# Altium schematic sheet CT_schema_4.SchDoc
size 334 x 183 mm
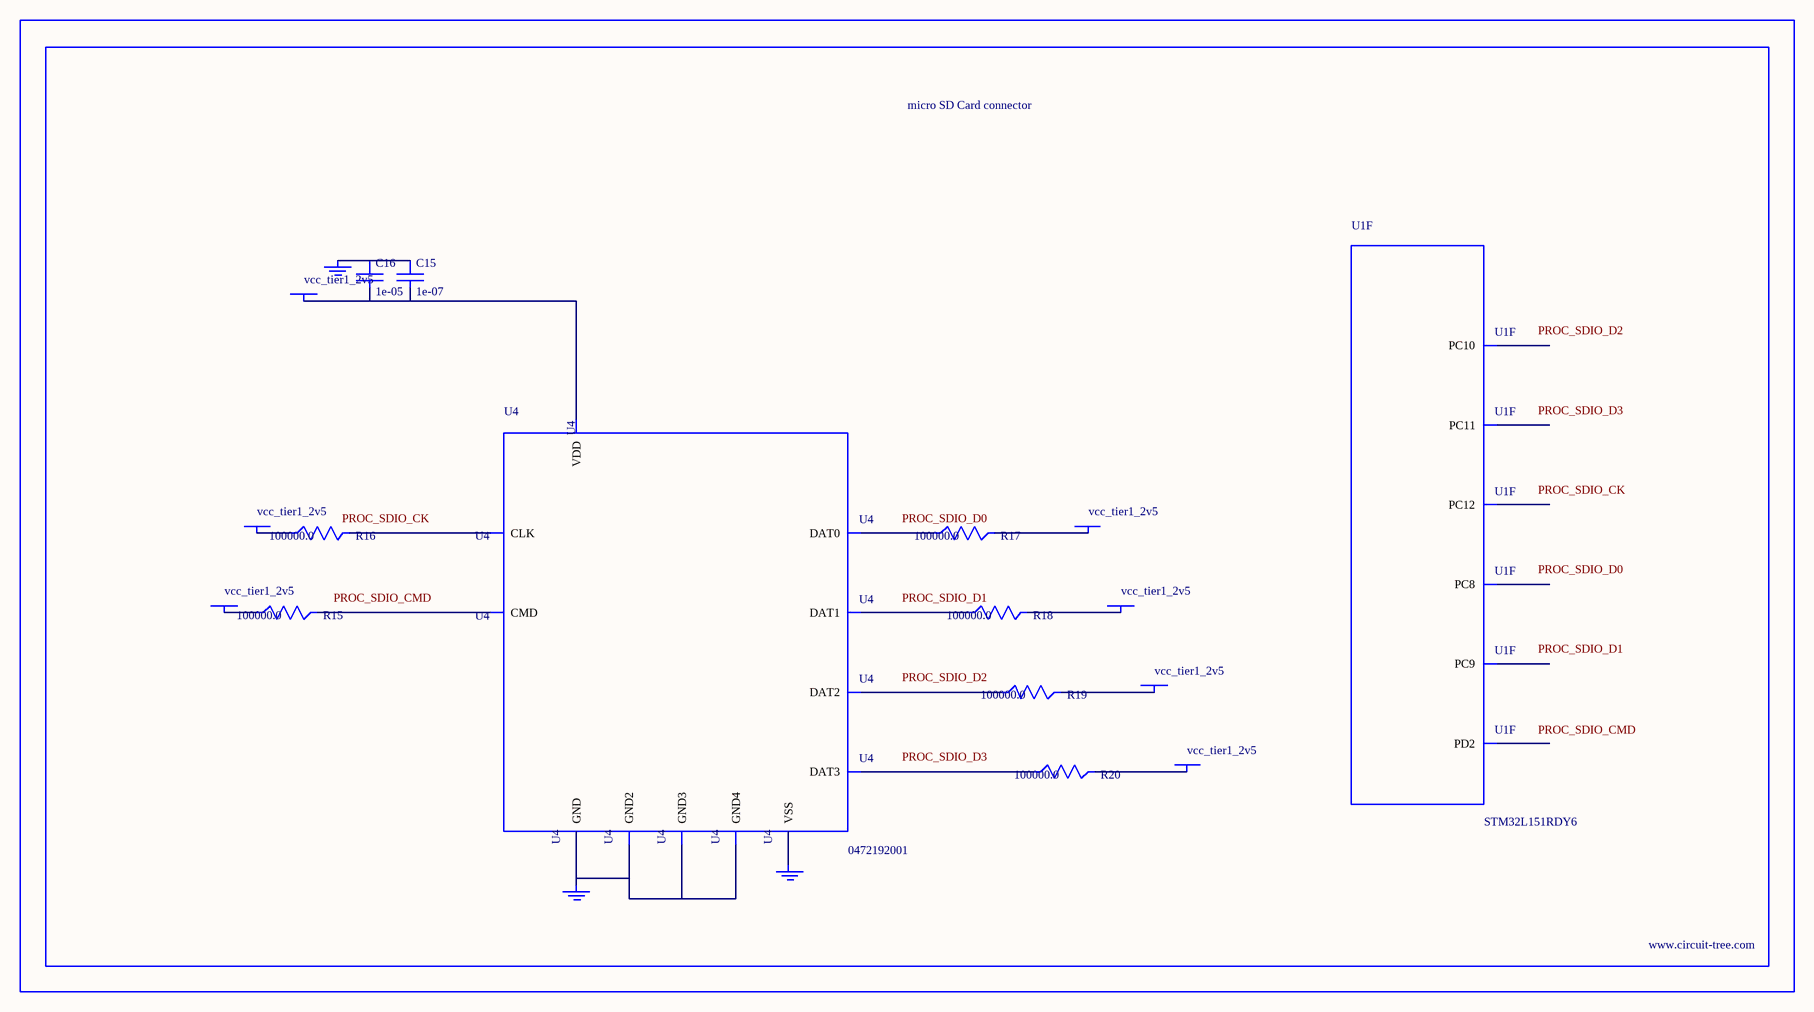
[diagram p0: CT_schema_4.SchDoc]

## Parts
BORDER3  (no value)
C15  1e-07  [C0402]
C16  1e-05  [C0805]
GND_INSTANCE_3_0  (no value)
GND_INSTANCE_3_1  (no value)
GND_INSTANCE_3_2  (no value)
POWER_INSTANCE_3_0  vcc_tier1_2v5
POWER_INSTANCE_3_1  vcc_tier1_2v5
POWER_INSTANCE_3_2  vcc_tier1_2v5
POWER_INSTANCE_3_3  vcc_tier1_2v5
POWER_INSTANCE_3_4  vcc_tier1_2v5
POWER_INSTANCE_3_5  vcc_tier1_2v5
POWER_INSTANCE_3_6  vcc_tier1_2v5
R15  100000.0  [R0603]
R16  100000.0  [R0603]
R17  100000.0  [R0603]
R18  100000.0  [R0603]
R19  100000.0  [R0603]
R20  100000.0  [R0603]
U1  STM32L151RDY6  [WLCSP64]  (part F of 8)
U4  0472192001  [MOLEX_47219-2001]

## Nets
NetC15_1: C15.1 C16.1 GND_INSTANCE_3_0.0(GND)
NetC15_2: C15.2 C16.2 POWER_INSTANCE_3_3.0(PWR) U4.4(VDD)
NetGND_INSTANCE_3_1_0: GND_INSTANCE_3_1.0(GND) U4.6(VSS)
NetGND_INSTANCE_3_2_0: GND_INSTANCE_3_2.0(GND) U4.G1(GND) U4.G2(GND2) U4.G3(GND3) U4.G4(GND4)
NetPOWER_INSTANCE_3_0_0: POWER_INSTANCE_3_0.0(PWR) R19.2
NetPOWER_INSTANCE_3_1_0: POWER_INSTANCE_3_1.0(PWR) R20.2
NetPOWER_INSTANCE_3_2_0: POWER_INSTANCE_3_2.0(PWR) R15.1
NetPOWER_INSTANCE_3_4_0: POWER_INSTANCE_3_4.0(PWR) R16.1
NetPOWER_INSTANCE_3_5_0: POWER_INSTANCE_3_5.0(PWR) R17.2
NetPOWER_INSTANCE_3_6_0: POWER_INSTANCE_3_6.0(PWR) R18.2
NetR15_2: R15.2 U4.3(CMD)
NetR16_2: R16.2 U4.5(CLK)
NetR17_1: R17.1 U4.7(DAT0)
NetR18_1: R18.1 U4.8(DAT1)
NetR19_1: R19.1 U4.1(DAT2)
NetR20_1: R20.1 U4.2(DAT3)

Not connected (* = marked no-connect by the designer): U1 A2(PC10) A3(PD2) B3(PC11) C4(PC12) D1(PC9) E3(PC8)

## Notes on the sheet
- Labels drawn without touching a wire or pin: PROC_SDIO_CK, PROC_SDIO_CMD, PROC_SDIO_D0, PROC_SDIO_D1, PROC_SDIO_D2, PROC_SDIO_D3

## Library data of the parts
BORDER3 = BORDER_PAGE3
C15 = C0402C104K3RACTU
C16 = C0805C106K8RACTU
GND_INSTANCE_3_0-GND_INSTANCE_3_2 = GND
POWER_INSTANCE_3_0-POWER_INSTANCE_3_6 = PWR
R15-R20 = RC0603JR-07100KL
